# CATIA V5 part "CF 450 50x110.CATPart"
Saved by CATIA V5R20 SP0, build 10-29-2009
Part number: CF 450 50x110
Definition: NONE
Nomenclature: CF 450 50x110
Source: Unknown
Description: CF 450 50x110
Bounding box of the stored display mesh (mm): x -39.5 to 39.5, y 0 to 110, z -39.5 to 39.5
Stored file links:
  C:\Users\Utente\Desktop\IO LAVORO\3D X SITO CF\X SITO\CF 450\CF 450 50x110.CATPart
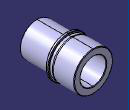
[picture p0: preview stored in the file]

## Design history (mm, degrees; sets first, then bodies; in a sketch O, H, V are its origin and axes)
Body1 "CF 450 50x110" (main body)
  Solid1: solid without history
